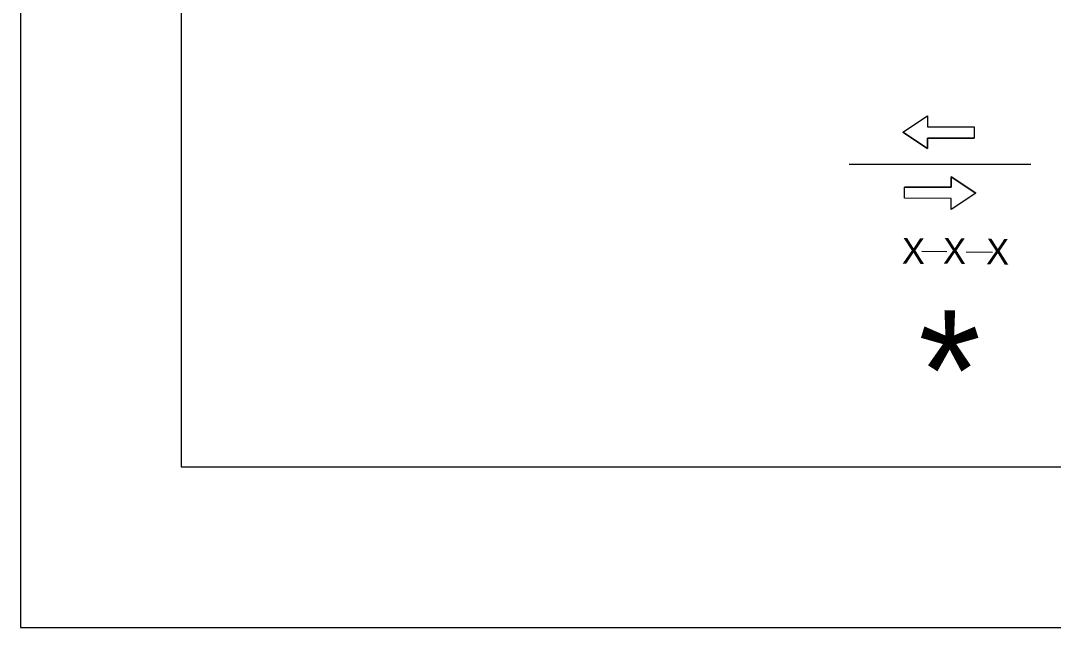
# Model space of a CAD drawing. Extents: x 1 to 1675, y -2 to 1113.
# Drawn here: x 1649.94 to 1659.58, y 1080.02 to 1085.68 of the extents above; entities that cross this region are included whole.
import ezdxf

# ---------------------------------------------------------------- set-up
doc = ezdxf.new("R2010")
doc.units = 0
for name, color, linetype in [('SH_Border', 7, 'Continuous'), ('SH_Cut_Line', 7, 'Continuous'), ('SH_Text', 7, 'Continuous'), ('SN_P_Signs', 7, 'Continuous')]:
    doc.layers.add(name, color=color, linetype=linetype)

msp = doc.modelspace()

# ---------------------------------------------------------------- linework, layer by layer
at = {"layer": 'SH_Border'}
msp.add_lwpolyline([(1651.4393, 1081.5171), (1673.9393, 1081.5171), (1673.9393, 1111.5171), (1651.4393, 1111.5171)], close=True, dxfattribs=at)
at = {"layer": 'SH_Cut_Line'}
msp.add_lwpolyline([(1649.9393, 1080.0171), (1675.4393, 1080.0171), (1675.4393, 1113.0171), (1649.9393, 1113.0171)], close=True, dxfattribs=at)
at = {"layer": 'SH_Text'}
for p, q in [((1658.178, 1084.6421), (1658.4078, 1084.7942)), ((1658.4078, 1084.7942), (1658.4076, 1084.6916)), ((1658.178, 1084.6421), (1658.4072, 1084.4889)), ((1658.4076, 1084.6916), (1658.8433, 1084.6907)), ((1658.8433, 1084.6907), (1658.8431, 1084.5863)), ((1658.4072, 1084.4889), (1658.4074, 1084.5872)), ((1658.4074, 1084.5872), (1658.8431, 1084.5863)), ((1659.3713, 1084.341), (1657.6745, 1084.341)), ((1658.6283, 1084.2264), (1658.6281, 1084.1282)), ((1658.8574, 1084.0733), (1658.6283, 1084.2264)), ((1658.1922, 1084.0247), (1658.1924, 1084.1291)), ((1658.6281, 1084.1282), (1658.1924, 1084.1291)), ((1658.8574, 1084.0733), (1658.6276, 1083.9212)), ((1658.6278, 1084.0238), (1658.1922, 1084.0247)), ((1658.6276, 1083.9212), (1658.6278, 1084.0238))]:
    msp.add_line(p, q, dxfattribs=at)
for points in [[(1658.8431, 1084.5863), (1658.4074, 1084.5872), (1658.4072, 1084.4889), (1658.178, 1084.642), (1658.4078, 1084.7942), (1658.4076, 1084.6916), (1658.8433, 1084.6907)], [(1658.1924, 1084.1291), (1658.6281, 1084.1282), (1658.6283, 1084.2264), (1658.8574, 1084.0733), (1658.6276, 1083.9212), (1658.6278, 1084.0238), (1658.1922, 1084.0247)]]:
    msp.add_lwpolyline(points, close=True, dxfattribs=at)
at = {"layer": 'SN_P_Signs'}
for p, q in [((1658.3528, 1083.5304), (1658.587, 1083.5273)), ((1658.7672, 1083.525), (1659.0135, 1083.5218))]:
    msp.add_line(p, q, dxfattribs=at)

# ---------------------------------------------------------------- texts
at = {"layer": 'SH_Text'}
msp.add_text('*', height=1.1232, dxfattribs=at).set_placement((1658.3214, 1081.8562))
at = {"layer": 'SN_P_Signs'}
for p in [(1658.1674, 1083.4134), (1658.5513, 1083.4134), (1658.9538, 1083.4081)]:
    msp.add_text('X', height=0.24, rotation=359.25135, dxfattribs=at).set_placement(p)

doc.saveas('drawing.dxf')
